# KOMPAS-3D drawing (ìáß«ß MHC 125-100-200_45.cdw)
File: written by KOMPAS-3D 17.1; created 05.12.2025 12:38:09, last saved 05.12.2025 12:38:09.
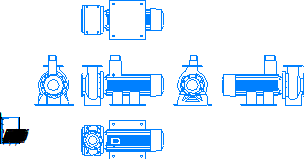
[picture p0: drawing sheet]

Sheet 1: A4, portrait

Title block, sheet 1: name: Насос MHC 125-100-200_45 / 45 кВт 3х380В; material: Сталь 10  ГОСТ 1050-88; mass: 334,84; sheets: 1; sheet format: A4

Views: Проекционный вид 2, Проекционный вид 3, Проекционный вид 4, Проекционный вид 5, Проекционный вид 6
Referenced files in \\adlc.lan\data\АДЛ_ПКД\3D-модели\ADL production\Насосы ГРАНПАМП\Насосы ГРАНПАМП серии МНС\KOMPAS 3D\: Насос MHC 125-100-200_45.m3d
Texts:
  Andrey
  АДЛ
Dimensions and other numbers on the sheet: 1:1; 1; 45 кВт 3х380В; 334,84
